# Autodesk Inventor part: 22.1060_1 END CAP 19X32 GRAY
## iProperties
Created: 2007-01
Part Number: 22.1060_1 END CAP 19X32 GRAY
Document SubType Name: Modeling
Designer: Andy Moles
Material: ABS Plastic
Density: 1.06 g/cm^3
Mass: 2.14066 g
Surface Area: 17.656 cm^2
Volume: 2.01949 cm^3
Author: Andy Moles
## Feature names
1. Extrusion1
2. Fillet1
3. Fillet2
4. Extrusion2
5. Fillet3
6. Extrusion3
7. Fillet4
